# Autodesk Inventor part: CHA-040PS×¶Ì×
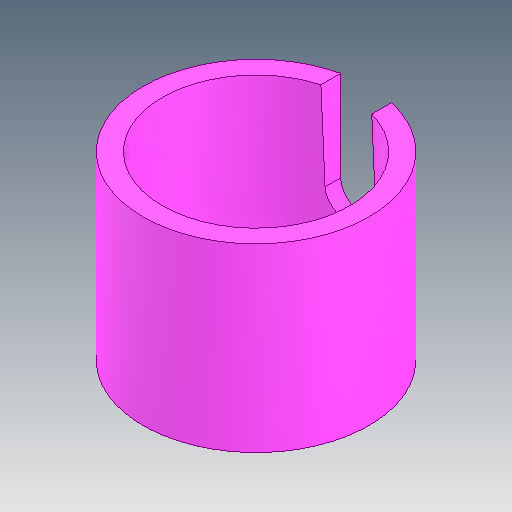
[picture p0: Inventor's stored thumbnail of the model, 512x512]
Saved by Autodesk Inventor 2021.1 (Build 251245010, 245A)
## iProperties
Created: 2021-05
Part Number: CHA-040PS×¶Ì×
Material: Ogólny
Document SubType Name: Modeling
Designer: user
Density: 1 g/cm^3
Appearance: Domyślna
Author: user
Revision Number: ÈÎºÎ
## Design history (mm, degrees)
feature "ÇÐ³ý-À­Éì1"
node "Bryła1"
